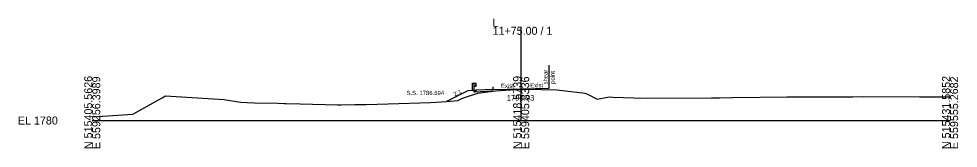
# Model space of a CAD drawing. Extents: x -26 to 1303, y -10 to 9545.
# Drawn here: x -25.7 to 302.8, y 3990.3 to 4035.6 of the extents above; entities that cross this region are included whole.
import ezdxf

# ---------------------------------------------------------------- set-up
doc = ezdxf.new("R2010")
doc.units = 0
for name, color, linetype in [('Exist Cross Section Cell', 7, 'Continuous'), ('Exist XS Center Line Elevation Label', 7, 'Continuous'), ('Exist XS Ground Line', 7, 'Continuous'), ('Prop XS EOT Tick Mark', 7, 'Continuous'), ('Prop XS Finish Grade', 7, 'Continuous'), ('Prop XS Finish Grade Earthwork', 7, 'Continuous'), ('Prop XS Finish Grade Paved Shoulder', 7, 'Continuous'), ('Prop XS Finish Grade Pavement', 7, 'Continuous'), ('Prop XS Guardrail', 7, 'Continuous'), ('Prop XS Pvmt Edge Slope', 7, 'Continuous'), ('Prop XS SE Text', 7, 'Continuous'), ('Prop XS Shear Point Label', 7, 'Continuous'), ('Prop XS Side Slope Text', 7, 'Continuous'), ('Prop XS SS Elevation Text', 7, 'Continuous'), ('Prop XS Subgrade Earthwork', 7, 'Continuous')]:
    doc.layers.add(name, color=color, linetype=linetype)

msp = doc.modelspace()

# ---------------------------------------------------------------- linework, layer by layer
at = {"layer": 'Exist Cross Section Cell'}
for p, q in [((150, 4000), (150, 4032.78)), ((0, 4000), (150, 4000)), ((150, 4000), (300, 4000))]:
    msp.add_line(p, q, dxfattribs=at)
at = {"layer": 'Exist XS Ground Line'}
for p, q in [((24.41, 4007.95), (25.57, 4008.62)), ((25.57, 4008.62), (46.12, 4007.38)), ((129.45, 4007.84), (134.84, 4009.62)), ((134.84, 4009.62), (138.32, 4010.03)), ((138.32, 4010.03), (141, 4010.38)), ((141, 4010.38), (148.08, 4010.82)), ((148.08, 4010.82), (149.62, 4010.92)), ((149.62, 4010.92), (150.16, 4010.93)), ((150.16, 4010.93), (151.47, 4010.91)), ((151.47, 4010.91), (162.46, 4010.72)), ((162.46, 4010.72), (171.43, 4009.67)), ((171.43, 4009.67), (172.27, 4009.57)), ((172.27, 4009.57), (172.67, 4009.5)), ((172.67, 4009.5), (173.24, 4009.19)), ((173.24, 4009.19), (176.59, 4007.44)), ((176.59, 4007.44), (180.88, 4008.23)), ((180.88, 4008.23), (182.09, 4008.19)), ((182.09, 4008.19), (189.39, 4007.95)), ((223.91, 4007.99), (242.93, 4008.31)), ((242.93, 4008.31), (244.52, 4008.32)), ((244.52, 4008.32), (266, 4008.32)), ((266, 4008.32), (269.78, 4008.38)), ((269.78, 4008.38), (289.32, 4008.25)), ((289.32, 4008.25), (294.82, 4008.28)), ((294.82, 4008.28), (300, 4008.27)), ((14.15, 4002.23), (24.41, 4007.95)), ((46.12, 4007.38), (51.84, 4006.37)), ((51.84, 4006.37), (54.12, 4006.26)), ((54.12, 4006.26), (56.78, 4006.17)), ((56.78, 4006.17), (64.86, 4006.01)), ((64.86, 4006.01), (67.09, 4005.98)), ((67.09, 4005.98), (67.87, 4005.96)), ((67.87, 4005.96), (72.67, 4005.84)), ((72.67, 4005.84), (85.71, 4005.51)), ((85.71, 4005.51), (86.97, 4005.52)), ((86.97, 4005.52), (91.8, 4005.6)), ((91.8, 4005.6), (95.81, 4005.64)), ((95.81, 4005.64), (103.46, 4005.88)), ((103.46, 4005.88), (118.3, 4006.35)), ((118.3, 4006.35), (123.92, 4006.69)), ((123.92, 4006.69), (127.83, 4006.97)), ((127.83, 4006.97), (129.45, 4007.84)), ((189.39, 4007.95), (191.85, 4007.87)), ((191.85, 4007.87), (216.54, 4007.9)), ((216.54, 4007.9), (218.96, 4007.9)), ((218.96, 4007.9), (219.39, 4007.9)), ((219.39, 4007.9), (223.91, 4007.99)), ((0, 4001.3), (7.18, 4001.76)), ((7.18, 4001.76), (14.15, 4002.23))]:
    msp.add_line(p, q, dxfattribs=at)
at = {"layer": 'Prop XS EOT Tick Mark'}
for p, q in [((140.17, 4010.82), (140.17, 4011.82)), ((159.74, 4011.27), (159.74, 4012.27))]:
    msp.add_line(p, q, dxfattribs=at)
at = {"layer": 'Prop XS Finish Grade'}
msp.add_line((134.3, 4010.62), (133.27, 4010.54), dxfattribs=at)
at = {"layer": 'Prop XS Finish Grade Earthwork'}
for p, q in [((131.3, 4010.38), (123.92, 4006.69)), ((133.27, 4010.54), (131.3, 4010.38))]:
    msp.add_line(p, q, dxfattribs=at)
at = {"layer": 'Prop XS Finish Grade Paved Shoulder'}
msp.add_line((140.17, 4010.82), (134.3, 4010.62), dxfattribs=at)
at = {"layer": 'Prop XS Finish Grade Pavement'}
for p, q in [((140.17, 4010.82), (150, 4011.05)), ((150, 4011.05), (159.74, 4011.27))]:
    msp.add_line(p, q, dxfattribs=at)
at = {"layer": 'Prop XS Guardrail'}
for p, q in [((132.98, 4013.04), (133.48, 4013.04)), ((132.98, 4010.52), (132.98, 4013.04)), ((133.48, 4013.04), (133.98, 4013.04)), ((133.48, 4013.04), (133.48, 4010.55)), ((133.98, 4011.91), (133.48, 4011.91)), ((133.98, 4013.04), (134.27, 4012.84)), ((134.27, 4012.72), (133.98, 4012.52)), ((133.98, 4012.52), (133.98, 4012.43)), ((133.98, 4012.43), (134.27, 4012.23)), ((134.27, 4012.11), (133.98, 4011.91)), ((134.27, 4012.84), (134.3, 4012.78)), ((134.3, 4012.78), (134.27, 4012.72)), ((134.27, 4012.23), (134.3, 4012.17)), ((134.3, 4012.17), (134.27, 4012.11))]:
    msp.add_line(p, q, dxfattribs=at)
at = {"layer": 'Prop XS Pvmt Edge Slope'}
msp.add_line((134.3, 4010.62), (133.85, 4009.96), dxfattribs=at)
at = {"layer": 'Prop XS Shear Point Label'}
msp.add_line((159.74, 4011.27), (159.74, 4019.37), dxfattribs=at)
at = {"layer": 'Prop XS Subgrade Earthwork'}
for p, q in [((133.85, 4009.96), (133.27, 4010.54)), ((139.62, 4010.24), (133.85, 4009.96)), ((140.17, 4010.28), (139.62, 4010.24)), ((140.17, 4010.27), (140.17, 4010.28))]:
    msp.add_line(p, q, dxfattribs=at)

# ---------------------------------------------------------------- texts
at = {"layer": 'Exist Cross Section Cell'}
for s, p in [('L', (140, 4032.78)), ('11+75.00 / 1', (140, 4029.98)), ('EL 1780', (-26, 3998.6))]:
    msp.add_text(s, height=2.8, dxfattribs=at).set_placement(p)
for s, p in [('N 515405.5626', (0, 3990)), ('E 559256.3989', (2.8, 3990)), ('N 515418.5739', (150, 3990)), ('E 559405.8336', (152.8, 3990)), ('N 515431.5852', (300, 3990)), ('E 559555.2682', (302.8, 3990))]:
    msp.add_text(s, height=2.8, rotation=90, dxfattribs=at).set_placement(p)
at = {"layer": 'Exist XS Center Line Elevation Label'}
msp.add_text('1790.93', height=2, dxfattribs=at).set_placement((144.94, 4006.93))
at = {"layer": 'Prop XS SE Text'}
for p in [(142.96, 4011.35), (153.18, 4011.54)]:
    msp.add_text('Exist', height=1.5, rotation=1.3214, dxfattribs=at).set_placement(p)
at = {"layer": 'Prop XS Shear Point Label'}
for s, p in [('shear', (159.23, 4012.61)), (' point', (161.67, 4012.22))]:
    msp.add_text(s, height=1.5, rotation=90, dxfattribs=at).set_placement(p)
at = {"layer": 'Prop XS Side Slope Text'}
msp.add_text('2:1', height=1.5, rotation=26.5651, dxfattribs=at).set_placement((126.76, 4008.4))
at = {"layer": 'Prop XS SS Elevation Text'}
msp.add_text('S.S. 1786.694', height=1.5, dxfattribs=at).set_placement((109.92, 4008.88))

doc.saveas('drawing.dxf')
